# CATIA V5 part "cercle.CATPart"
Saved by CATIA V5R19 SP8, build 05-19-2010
Part number: cercle
Bounding box of the stored display mesh (mm): x 0 to 9, y -15 to 15, z -15 to 15
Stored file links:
  F:\Projet3\cercle.CATPart
  F:\Projet3\Produit1.CATProduct
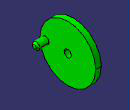
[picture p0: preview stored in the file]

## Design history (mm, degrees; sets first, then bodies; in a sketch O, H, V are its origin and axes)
Parameters
  Longueur = 10 mm
Body1 (main body)
  Sketch1 on yz-plane, origin (0, 0, 0), H (0, 1, 0), V (0, 0, 1)
    circle A1 centre (0, 0) radius 15
    point P1 (0, 0)
    radius A1 = 15 {= Longueur *1.5}
    coincidence: P1 V, P1 O
  Pad1: profile Sketch1, direction (1, 0, 0), length 3 {= Longueur *0.3}
  Sketch2 on end face of Pad1, origin (3, 0, 0), H (0, 1, 0), V (0, 0, 1)
  Sketch3 on end face of Pad1, origin (3, 0, 0), H (0, 1, 0), V (0, 0, 1)
    circle A1 centre (0, 0) radius 2
    point P1 (0, 0)
    radius A1 = 2 {= Longueur *0.2}
    coincidence: P1 O
  Pocket1: profile Sketch3, direction (-1, 0, 0), through (limit type 3), offset 0 {= Longueur *0}
  Sketch4 on end face of Pad1, origin (3, 0, 0), H (0, 1, 0), V (0, 0, 1)
    circle A1 centre (-12, 0) radius 2
    point P1 (-12, 0)
    point P2 (-10, 0)
    distance P1 V = 12 {= Longueur *1.2}
    radius A1 = 2 {= Longueur *0.2}
    coincidence: P1 H, A1 P2, P2 H
  Pad2: profile Sketch4, direction (1, 0, 0), length 6 {= Longueur *0.6}
  Chamfer1: length 1 {= Longueur *0.1}, angle 45, on edge [face of Pad2 from Sketch4.A1 | end face of Pad2]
